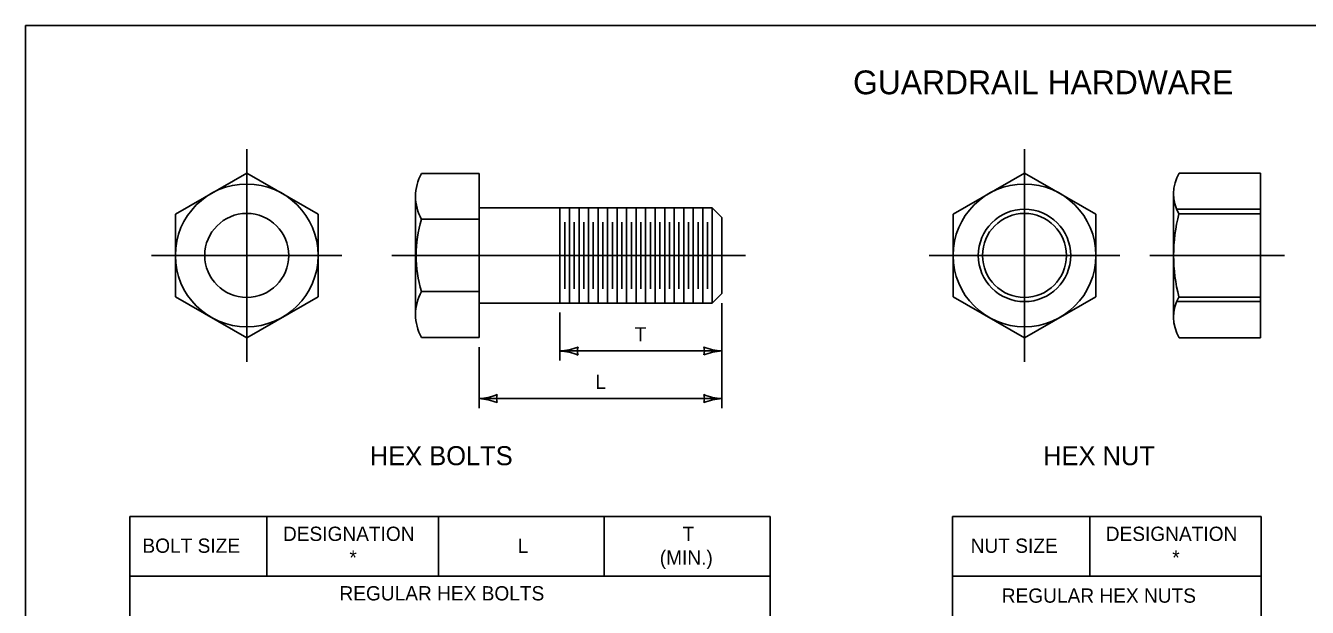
# Model space of a CAD drawing. Extents: x 49991.4 to 50021, y 49987.6 to 50011.4.
# Drawn here: x 49999.38 to 50004.77, y 49996.55 to 49999 of the extents above; entities that cross this region are included whole.
import ezdxf

# ---------------------------------------------------------------- set-up
doc = ezdxf.new("R2010")
doc.units = 0
for name, color, linetype in [('Level 1', 7, 'Continuous'), ('Level 2', 7, 'Continuous'), ('Level 3', 7, 'Continuous'), ('Level 4', 7, 'Continuous'), ('Level 5', 7, 'Continuous')]:
    doc.layers.add(name, color=color, linetype=linetype)

msp = doc.modelspace()

# ---------------------------------------------------------------- linework, layer by layer
at = {"layer": 'Level 1'}
for p, q in [((50000.3126, 49998.3799), (50000.0126, 49998.2067)), ((50000.6126, 49998.2067), (50000.3126, 49998.3799)), ((50001.047, 49998.3782), (50001.2886, 49998.3782)), ((50001.2886, 49997.6887), (50001.2886, 49998.3782)), ((50003.5803, 49998.3799), (50003.2803, 49998.2067)), ((50003.8803, 49998.2067), (50003.5803, 49998.3799)), ((50004.23, 49998.3799), (50004.5721, 49998.3799)), ((50004.5721, 49997.687), (50004.5721, 49998.3799)), ((50004.2068, 49997.7739), (50004.2068, 49998.2925)), ((50001.0216, 49997.7862), (50001.0216, 49998.2808)), ((50000.0126, 49997.8602), (50000.0126, 49998.2067)), ((50000.6126, 49997.8602), (50000.6126, 49998.2067)), ((50001.047, 49998.1852), (50001.2886, 49998.1852)), ((50001.2886, 49998.2335), (50002.2686, 49998.2335)), ((50001.6286, 49997.8335), (50001.6286, 49998.2335)), ((50001.6686, 49997.8335), (50001.6686, 49998.2335)), ((50001.7086, 49997.8335), (50001.7086, 49998.2335)), ((50001.7486, 49997.8335), (50001.7486, 49998.2335)), ((50001.7886, 49997.8335), (50001.7886, 49998.2335)), ((50001.8286, 49997.8335), (50001.8286, 49998.2335)), ((50001.8686, 49997.8335), (50001.8686, 49998.2335)), ((50001.9086, 49997.8335), (50001.9086, 49998.2335)), ((50001.9486, 49997.8335), (50001.9486, 49998.2335)), ((50001.9886, 49997.8335), (50001.9886, 49998.2335)), ((50002.0286, 49997.8335), (50002.0286, 49998.2335)), ((50002.0686, 49997.8335), (50002.0686, 49998.2335)), ((50002.1086, 49997.8335), (50002.1086, 49998.2335)), ((50002.1486, 49997.8335), (50002.1486, 49998.2335)), ((50002.1886, 49997.8335), (50002.1886, 49998.2335)), ((50002.2286, 49997.8335), (50002.2286, 49998.2335)), ((50002.2686, 49997.8335), (50002.2686, 49998.2335)), ((50002.2686, 49998.2335), (50002.3086, 49998.1935)), ((50002.3086, 49997.8735), (50002.3086, 49998.1935)), ((50003.2803, 49997.8602), (50003.2803, 49998.2067)), ((50003.8803, 49997.8602), (50003.8803, 49998.2067)), ((50004.2291, 49998.2081), (50004.5721, 49998.2081)), ((50001.6486, 49997.8935), (50001.6486, 49998.1735)), ((50001.6886, 49997.8935), (50001.6886, 49998.1735)), ((50001.7286, 49997.8935), (50001.7286, 49998.1735)), ((50001.7686, 49997.8935), (50001.7686, 49998.1735)), ((50001.8086, 49997.8935), (50001.8086, 49998.1735)), ((50001.8486, 49997.8935), (50001.8486, 49998.1735)), ((50001.8886, 49997.8935), (50001.8886, 49998.1735)), ((50001.9286, 49997.8935), (50001.9286, 49998.1735)), ((50001.9686, 49997.8935), (50001.9686, 49998.1735)), ((50002.0086, 49997.8935), (50002.0086, 49998.1735)), ((50002.0486, 49997.8935), (50002.0486, 49998.1735)), ((50002.0886, 49997.8935), (50002.0886, 49998.1735)), ((50002.1286, 49997.8935), (50002.1286, 49998.1735)), ((50002.1686, 49997.8935), (50002.1686, 49998.1735)), ((50002.2086, 49997.8935), (50002.2086, 49998.1735)), ((50002.2486, 49997.8935), (50002.2486, 49998.1735)), ((50001.047, 49997.8817), (50001.2886, 49997.8817)), ((50002.2686, 49997.8335), (50002.3086, 49997.8735)), ((50000.3126, 49997.687), (50000.0126, 49997.8602)), ((50000.6126, 49997.8602), (50000.3126, 49997.687)), ((50001.2886, 49997.8335), (50002.2686, 49997.8335)), ((50003.5803, 49997.687), (50003.2803, 49997.8602)), ((50003.8803, 49997.8602), (50003.5803, 49997.687)), ((50004.2291, 49997.8588), (50004.5721, 49997.8588)), ((50001.047, 49997.6887), (50001.2886, 49997.6887)), ((50004.23, 49997.687), (50004.5721, 49997.687))]:
    msp.add_line(p, q, dxfattribs=at)
msp.add_lwpolyline([(49999.3835, 49998.9992), (50016.7501, 49998.9992), (50016.7501, 49987.7988), (49999.3835, 49987.7988)], close=True, dxfattribs=at)
for centre, radius in [((50000.3126, 49998.0335), 0.3), ((50003.5803, 49998.0335), 0.3), ((50003.5803, 49998.0335), 0.1765)]:
    msp.add_circle(centre, radius, dxfattribs=at)
for centre, radius, start, end in [((50001.2179, 49998.2817), 0.1963, 150.5528, 209.4472), ((50004.38, 49998.2933), 0.1732, 150, 209.4472), ((50001.5471, 49998.0335), 0.5227, 163.1225, 196.8779), ((50004.8996, 49998.0335), 0.6928, 165.3984, 194.6015), ((50001.2179, 49997.7852), 0.1963, 150.5529, 209.4483), ((50004.38, 49997.7736), 0.1732, 150.5529, 210.0001)]:
    msp.add_arc(centre, radius, start, end, dxfattribs=at)
at = {"layer": 'Level 2'}
for p, q in [((49999.8208, 49996.936), (50002.5121, 49996.936)), ((49999.8208, 49994.436), (49999.8208, 49996.936)), ((50000.3975, 49996.686), (50000.3975, 49996.936)), ((50001.1175, 49996.686), (50001.1175, 49996.936)), ((50001.8148, 49996.686), (50001.8148, 49996.936)), ((50002.5121, 49994.436), (50002.5121, 49996.936)), ((50003.2779, 49996.936), (50004.5745, 49996.936)), ((50003.2779, 49994.926), (50003.2779, 49996.936)), ((50003.8545, 49996.686), (50003.8545, 49996.936)), ((50004.5745, 49996.936), (50004.5745, 49994.926)), ((49999.8208, 49996.686), (50002.5121, 49996.686)), ((50003.2779, 49996.686), (50004.5745, 49996.686))]:
    msp.add_line(p, q, dxfattribs=at)
at = {"layer": 'Level 3'}
for p, q in [((50002.3086, 49997.8335), (50002.3086, 49997.3919)), ((50001.6286, 49997.7935), (50001.6286, 49997.5919)), ((50001.2886, 49997.6487), (50001.2886, 49997.3919)), ((50002.3086, 49997.6319), (50001.6286, 49997.6319)), ((50002.3086, 49997.4319), (50001.2886, 49997.4319))]:
    msp.add_line(p, q, dxfattribs=at)
for centre, radius, start, end in [((50001.6171, 49997.8646), 0.233, 272.8273, 292.0772), ((50001.7568, 49997.6319), 0.0548, 162.1388, 197.8612), ((50002.3178, 49997.854), 0.2223, 247.456, 267.6395), ((50002.1804, 49997.6319), 0.0548, 342.1388, 17.8612), ((50001.6194, 49997.4097), 0.2223, 67.456, 87.6395), ((50002.3201, 49997.3992), 0.233, 92.8273, 112.0772), ((50001.2771, 49997.6646), 0.233, 272.8273, 292.0772), ((50001.2794, 49997.2097), 0.2223, 67.456, 87.6395), ((50001.4168, 49997.4319), 0.0548, 162.1388, 197.8612), ((50002.3178, 49997.654), 0.2223, 247.456, 267.6395), ((50002.1804, 49997.4319), 0.0548, 342.1388, 17.8612), ((50002.3201, 49997.1992), 0.233, 92.8273, 112.0772)]:
    msp.add_arc(centre, radius, start, end, dxfattribs=at)
at = {"layer": 'Level 4'}
for p, q in [((50004.2197, 49998.2276), (50004.5721, 49998.2276)), ((50004.2197, 49997.8393), (50004.5721, 49997.8393))]:
    msp.add_line(p, q, dxfattribs=at)
for centre, radius in [((50000.3126, 49998.0335), 0.1765), ((50003.5803, 49998.0335), 0.1941)]:
    msp.add_circle(centre, radius, dxfattribs=at)
at = {"layer": 'Level 5'}
for p, q in [((50000.3126, 49997.587), (50000.3126, 49998.4799)), ((50003.5803, 49997.587), (50003.5803, 49998.4799)), ((50000.7126, 49998.0335), (49999.9126, 49998.0335)), ((50000.9216, 49998.0335), (50002.4086, 49998.0335)), ((50003.9803, 49998.0335), (50003.1803, 49998.0335)), ((50004.1068, 49998.0335), (50004.6721, 49998.0335))]:
    msp.add_line(p, q, dxfattribs=at)

# ---------------------------------------------------------------- texts
at = {"layer": 'Level 2'}
for s, height, p in [('GUARDRAIL HARDWARE', 0.1, (50002.8601, 49998.7108)), ('T', 0.06, (50001.9426, 49997.6719)), ('L', 0.06, (50001.7774, 49997.4719)), ('HEX BOLTS', 0.08, (50000.8296, 49997.1519)), ('HEX NUT', 0.08, (50003.6586, 49997.1519)), ('DESIGNATION', 0.06, (50000.4647, 49996.8337)), ('T', 0.06, (50002.1438, 49996.8337)), ('DESIGNATION', 0.06, (50003.9218, 49996.8337)), ('BOLT SIZE', 0.06, (49999.8743, 49996.7838)), ('L', 0.06, (50001.4513, 49996.7837)), ('NUT SIZE', 0.06, (50003.3542, 49996.7837)), ('*', 0.06, (50000.7439, 49996.7337)), ('(MIN.)', 0.06, (50002.0479, 49996.7337)), ('*', 0.06, (50004.201, 49996.7337)), ('REGULAR HEX BOLTS', 0.06, (50000.7021, 49996.5837)), ('REGULAR HEX NUTS', 0.06, (50003.4849, 49996.574))]:
    msp.add_text(s, height=height, dxfattribs=at).set_placement(p)

doc.saveas('drawing.dxf')
